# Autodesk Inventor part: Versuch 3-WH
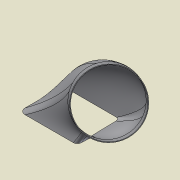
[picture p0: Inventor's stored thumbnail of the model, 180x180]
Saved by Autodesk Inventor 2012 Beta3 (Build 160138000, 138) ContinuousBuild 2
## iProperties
Created: 2011-05
Part Number: Versuch 3-WH
Material: Default
Document SubType Name: Modeling
Designer: Alex
Density: 1 g/cm^3
Author: Alex
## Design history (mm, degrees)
sketch "Skizze1"
  geometry: L1 (-14.5, 11)-(14.5, 11); L2 (14.5, 11)-(14.5, -11); L3 (14.5, -11)-(-14.5, -11); L4 (-14.5, -11)-(-14.5, 11); L5 (-24, 26)-(24, 26); L6 (24, 26)-(24, -26); L7 (24, -26)-(-24, -26); L8 (-24, -26)-(-24, 26); L9 (24, -26)-(60.94, 21.281); L10 (24, -26)-(84, -26); 1 further point
  constraints: 20 end point, 4 parallel, 3 horizontal, 2 perpendicular, 1 equal length
  dimensions: "d0" = 14.5 distance from line of point (0, 0) L4; "d1" = 14.5 distance from line of point (0, 0) L2; "d2" = 11 distance from line of point (0, 0) L1; "d3" = 11 distance from line of point (0, 0) L3; "d4" = 24 distance from line of point (0, 0) L8; "d5" = 24 distance from line of point (0, 0) L6; "d6" = 26 distance from line of point (0, 0) L5; "d7" = 26 distance from line of point (0, 0) L7; "d8" = 60 distance of L6.end L9.end; "d9" = 52 deg angle of L10 L9
workplane "Arbeitsebene1"
sketch "Skizze2"
  geometry: L1 (0, 0)-(18.16, 35.64); L2 (0, 0)-(40, 0); 1 further point
  constraints: 4 end point, 1 equal length, 1 horizontal
  dimensions: "d10" = 40 distance of L1.start L1.end; "d11" = 63 deg angle of L2 L1
workplane "Arbeitsebene2"
sketch "Skizze3"
  geometry: L1 (60.003, 0.017)-(60.003, 32.017); L2 (60.003, 32.017)-(43.003, 32.017); L3 (60.003, 0.017)-(19.818, 0.017); C1 r 14 at (43.003, 32.017); 1 further point
  constraints: 6 end point, 1 centre point, 1 coincident, 1 parallel, 1 perpendicular, 1 vertical
  dimensions: "d12" = 32 distance of L1.start L1.end; "d13" = 17 distance of L1.end L2.end; "d14" = 28 diameter of C1; "d18" = 32 distance from line of L2.end L3 (derived)
workplane "Arbeitsebene3"
extrude "Extrusion1" new body sketch "Skizze3" distance "d16" = 6; taper "d17" = 0 deg
feature "Körper verschieben1"
feature "Erhebung1" dims "d22" = 0, "d23" = 90 deg, "d24" = 10, "d25" = 90 deg
  node "Kanten1"
fillet "Rundung1" dims "d26" = 2
fillet "Rundung2" dims "d27" = 2
fillet "Rundung3" dims "d28" = 2
fillet "Rundung4" dims "d29" = 3
delete_face "Delete Face1"
feature "Stitch Surface2"
shell "Shell1" dims "d40" = 0.3
node "Volumenkörper1"
body "Srf6"
node "Edges1"
node "Edges2"
feature "LoftSrf1" dims "d36" = 90 deg, "d37" = 0, "d38" = 90 deg, "d39" = 10
other parameters: "d15" = 6, "d19" = 0, "d20" = 0
